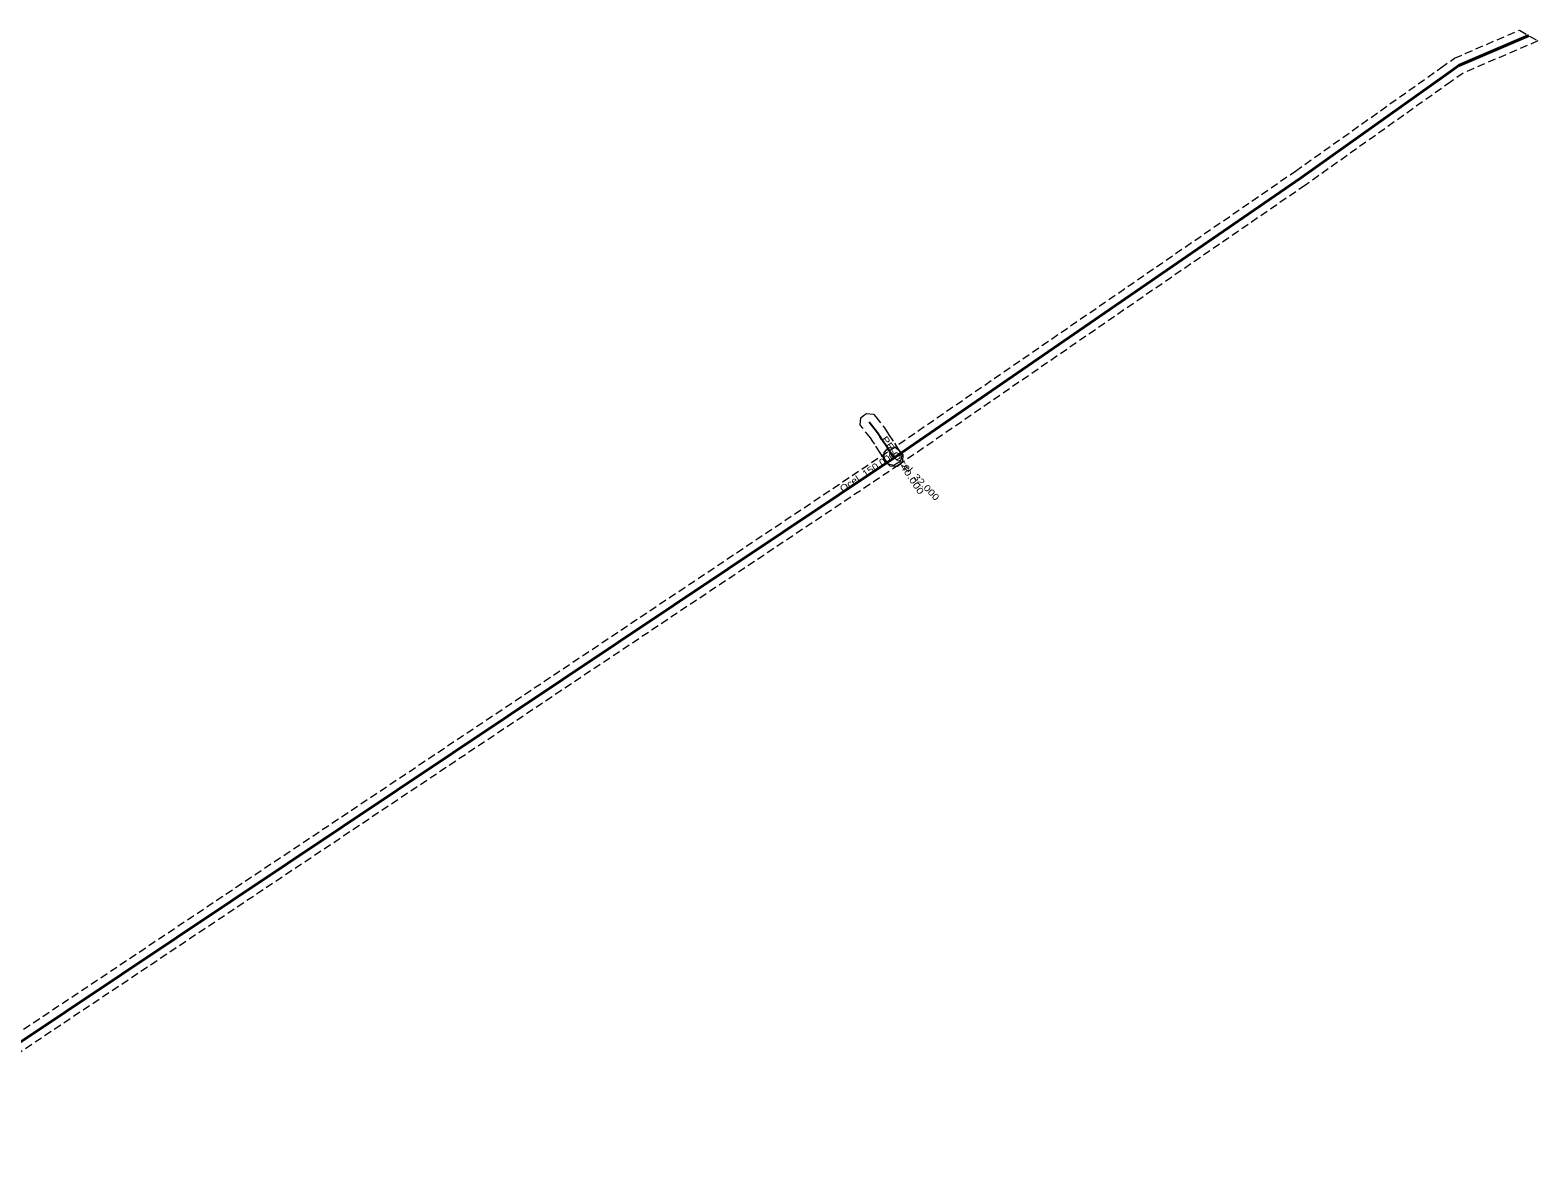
# Model space of a CAD drawing. Extents: x -640775 to -624586, y -1148563 to -1138811.
# Drawn here: x -640364.8 to -640189.2, y -1138943.3 to -1138810.7 of the extents above; entities that cross this region are included whole.
import ezdxf

# ---------------------------------------------------------------- set-up
doc = ezdxf.new("R2010")
doc.units = 0
doc.header["$LTSCALE"] = 0.3
doc.linetypes.add('MEDIUM_DASHED', pattern=[4.5, 3, -1.5])
doc.layers.add('1', color=7, linetype='MEDIUM_DASHED', lineweight=13)
doc.layers.add('24', color=7, linetype='Continuous', lineweight=40)
doc.layers.add('30', color=7, linetype='Continuous')

msp = doc.modelspace()

# ---------------------------------------------------------------- linework, layer by layer
at = {"layer": '1'}
for points in [[(-640191.344, -1138810.7), (-640189.215, -1138811.963), (-640197.927, -1138815.707), (-640199.338, -1138816.709), (-640216.297, -1138828.759), (-640263.638, -1138861.363), (-640385.804, -1138943.041), (-640386.149, -1138943.271), (-640386.961, -1138943.11), (-640387.191, -1138942.766), (-640387.421, -1138942.421), (-640387.26, -1138941.609), (-640386.916, -1138941.379), (-640264.762, -1138859.709), (-640217.443, -1138827.121), (-640200.496, -1138815.079), (-640198.913, -1138813.953)], [(-640264.218, -1138861.414), (-640265.022, -1138861.217), (-640265.237, -1138860.862), (-640265.523, -1138860.391), (-640265.813, -1138859.935), (-640266.461, -1138858.958), (-640266.676, -1138858.637), (-640266.958, -1138858.188), (-640267.9, -1138857.019), (-640268.16, -1138856.696), (-640268.072, -1138855.873), (-640267.75, -1138855.613), (-640267.427, -1138855.353), (-640266.604, -1138855.441), (-640266.344, -1138855.763), (-640265.326, -1138857.024), (-640264.996, -1138857.551), (-640264.797, -1138857.85), (-640264.135, -1138858.845), (-640263.823, -1138859.337), (-640263.527, -1138859.826), (-640263.312, -1138860.18), (-640263.509, -1138860.984), (-640263.864, -1138861.199)], [(-640263.813, -1138861.547), (-640264.641, -1138861.525), (-640264.926, -1138861.224), (-640265.108, -1138861.032), (-640265.393, -1138860.731), (-640265.371, -1138859.903), (-640265.07, -1138859.618), (-640264.769, -1138859.333), (-640263.941, -1138859.355), (-640263.656, -1138859.656), (-640263.474, -1138859.848), (-640263.189, -1138860.149), (-640263.211, -1138860.977), (-640263.512, -1138861.262)]]:
    msp.add_lwpolyline(points, close=True, dxfattribs=at)
at = {"layer": '24', "lineweight": 25}
msp.add_line((-640264.2, -1138860.536), (-640264.382, -1138860.344), dxfattribs=at)
at = {"layer": '24'}
for points in [[(-640216.87, -1138827.94), (-640199.917, -1138815.894), (-640198.42, -1138814.83), (-640190.28, -1138811.332)], [(-640386.36, -1138942.21), (-640264.2, -1138860.536), (-640216.87, -1138827.94)]]:
    msp.add_lwpolyline(points, dxfattribs=at)
at = {"layer": '24', "lineweight": 25}
for points in [[(-640265.836, -1138858.094), (-640266.142, -1138857.606), (-640267.122, -1138856.391)], [(-640264.382, -1138860.344), (-640264.673, -1138859.864), (-640264.974, -1138859.39), (-640265.629, -1138858.404), (-640265.836, -1138858.094)]]:
    msp.add_lwpolyline(points, dxfattribs=at)

# ---------------------------------------------------------------- texts
at = {"layer": '30'}
for s, rotation, width, p in [('PE-O, 40.000', 303.733, 1.3, (-640265.685, -1138858.32)), ('Ocel, 150.000', 33.766, 1.2, (-640270.202, -1138864.549)), ('Ocel, 32.000', 313.468, 1.25, (-640264.291, -1138860.44))]:
    msp.add_text(s, height=0.75, rotation=rotation, dxfattribs=dict(at, width=width)).set_placement(p)

doc.saveas('drawing.dxf')
